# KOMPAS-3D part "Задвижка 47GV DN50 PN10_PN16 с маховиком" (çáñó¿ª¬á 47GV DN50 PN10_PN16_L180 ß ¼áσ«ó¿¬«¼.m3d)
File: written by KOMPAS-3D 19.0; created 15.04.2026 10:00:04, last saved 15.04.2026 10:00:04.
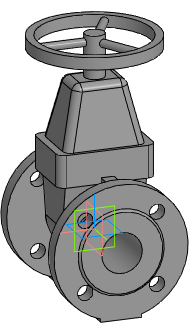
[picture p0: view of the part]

Document properties: Автор: Евгений; Полное имя файла: Z:\3.Личные\kachalov\3d для проектировщиков\2.1 Тип 47GV, 47GV.Z\Задвижка 47GV_DN40-DN600\stp_Задвижка 47GV\Задвижка 47GV DN50 PN10_PN16_L180 с маховиком.m3d

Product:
- Part/product: Задвижка 47GV DN50 PN10_PN16 с маховиком

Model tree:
1. Операция без истории:1  (labels: Задвижка 47GV DN50 PN10_PN16 с маховиком)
